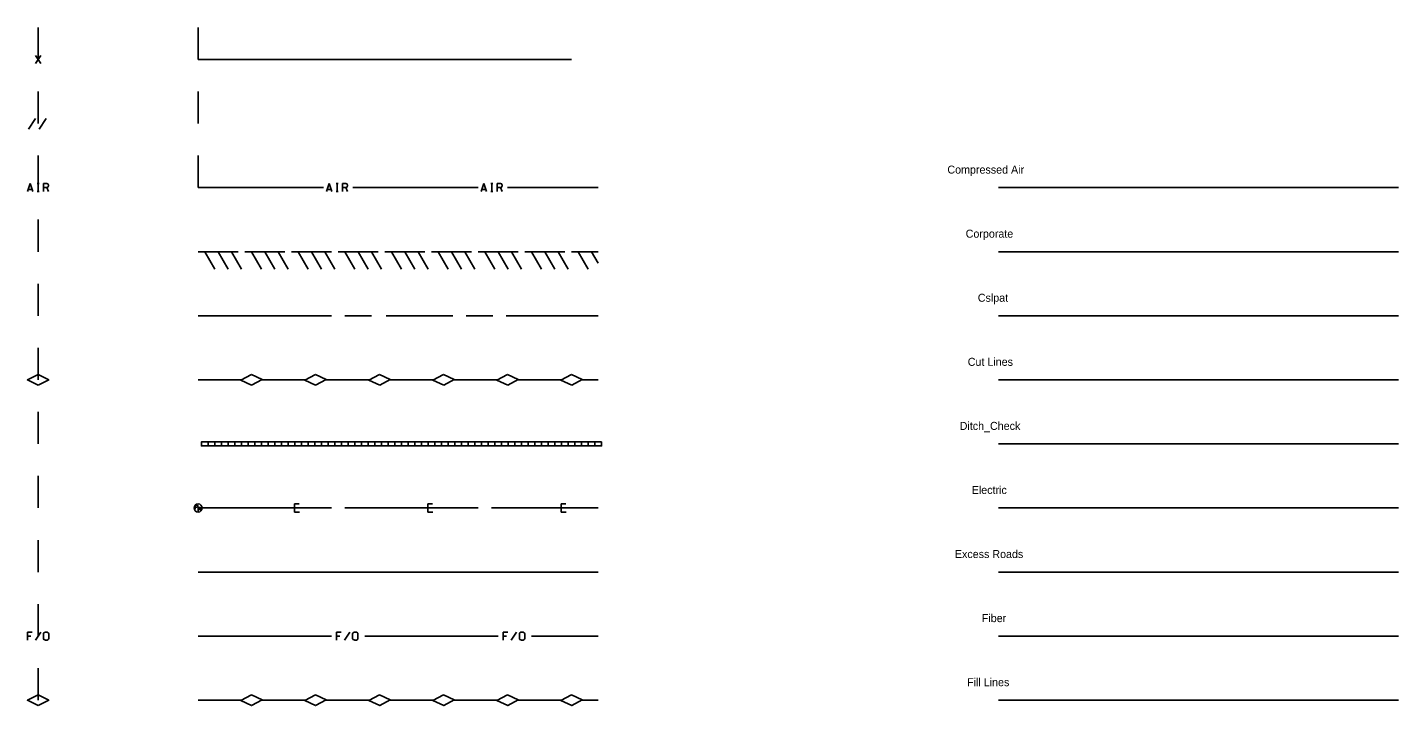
# Model space of a CAD drawing. Extents: x -0.01 to 0.85, y -1.76 to 0.02.
# Drawn here: x -0.007 to 0.85, y -0.403 to 0.02 of the extents above; entities that cross this region are included whole.
import ezdxf

# ---------------------------------------------------------------- set-up
doc = ezdxf.new("R2010")
doc.units = 0
doc.layers.add('Default', color=7, linetype='Continuous')

msp = doc.modelspace()

# ---------------------------------------------------------------- linework, layer by layer
at = {"layer": 'Default'}
for p, q in [((0, 0), (0, 0.02)), ((0.1, 0), (0.1, 0.02)), ((-0.00163, 0.0025), (0.00163, -0.0025)), ((-0.00163, -0.0025), (0.00163, 0.0025)), ((0.1, 0), (0.33333, 0)), ((0, -0.04), (0, -0.02)), ((0.1, -0.04), (0.1, -0.02)), ((-0.00597, -0.04347), (-0.00152, -0.03681)), ((0.0007, -0.04347), (0.00514, -0.03681)), ((0, -0.08), (0, -0.06)), ((0.1, -0.08), (0.1, -0.06)), ((-0.00667, -0.0825), (-0.005, -0.0775)), ((-0.00375, -0.08125), (-0.00625, -0.08125)), ((-0.005, -0.0775), (-0.00333, -0.0825)), ((-0.00062, -0.0775), (0.00062, -0.0775)), ((-0.00062, -0.0825), (0.00062, -0.0825)), ((0, -0.0775), (0, -0.0825)), ((0.00333, -0.0825), (0.00333, -0.0775)), ((0.00333, -0.0775), (0.00542, -0.0775)), ((0.00542, -0.07997), (0.00333, -0.07997)), ((0.00542, -0.07997), (0.00648, -0.0825)), ((0.1, -0.08), (0.17833, -0.08)), ((0.18022, -0.0825), (0.18188, -0.0775)), ((0.18313, -0.08125), (0.18063, -0.08125)), ((0.18188, -0.0775), (0.18355, -0.0825)), ((0.18626, -0.0775), (0.18751, -0.0775)), ((0.18626, -0.0825), (0.18751, -0.0825)), ((0.18688, -0.0775), (0.18688, -0.0825)), ((0.19022, -0.0825), (0.19022, -0.0775)), ((0.19022, -0.0775), (0.1923, -0.0775)), ((0.1923, -0.07997), (0.19022, -0.07997)), ((0.1923, -0.07997), (0.19337, -0.0825)), ((0.19667, -0.08), (0.275, -0.08)), ((0.27688, -0.0825), (0.27855, -0.0775)), ((0.2798, -0.08125), (0.2773, -0.08125)), ((0.27855, -0.0775), (0.28022, -0.0825)), ((0.28293, -0.0775), (0.28418, -0.0775)), ((0.28293, -0.0825), (0.28418, -0.0825)), ((0.28355, -0.0775), (0.28355, -0.0825)), ((0.28688, -0.0825), (0.28688, -0.0775)), ((0.28688, -0.0775), (0.28897, -0.0775)), ((0.28897, -0.07997), (0.28688, -0.07997)), ((0.28897, -0.07997), (0.29003, -0.0825)), ((0.29333, -0.08), (0.35, -0.08)), ((0.6, -0.08), (0.85, -0.08)), ((0, -0.12), (0, -0.1)), ((0.1, -0.12), (0.125, -0.12)), ((0.10417, -0.12), (0.11042, -0.13083)), ((0.1125, -0.12), (0.11875, -0.13083)), ((0.12083, -0.12), (0.12708, -0.13083)), ((0.12917, -0.12), (0.15417, -0.12)), ((0.13333, -0.12), (0.13958, -0.13083)), ((0.14167, -0.12), (0.14792, -0.13083)), ((0.15, -0.12), (0.15625, -0.13083)), ((0.15833, -0.12), (0.18333, -0.12)), ((0.1625, -0.12), (0.16875, -0.13083)), ((0.17083, -0.12), (0.17708, -0.13083)), ((0.17917, -0.12), (0.18542, -0.13083)), ((0.1875, -0.12), (0.2125, -0.12)), ((0.19167, -0.12), (0.19792, -0.13083)), ((0.2, -0.12), (0.20625, -0.13083)), ((0.20833, -0.12), (0.21458, -0.13083)), ((0.21667, -0.12), (0.24167, -0.12)), ((0.22083, -0.12), (0.22708, -0.13083)), ((0.22917, -0.12), (0.23542, -0.13083)), ((0.2375, -0.12), (0.24375, -0.13083)), ((0.24583, -0.12), (0.27083, -0.12)), ((0.25, -0.12), (0.25625, -0.13083)), ((0.25833, -0.12), (0.26458, -0.13083)), ((0.26667, -0.12), (0.27292, -0.13083)), ((0.275, -0.12), (0.3, -0.12)), ((0.27917, -0.12), (0.28542, -0.13083)), ((0.2875, -0.12), (0.29375, -0.13083)), ((0.29583, -0.12), (0.30208, -0.13083)), ((0.30417, -0.12), (0.32917, -0.12)), ((0.30833, -0.12), (0.31458, -0.13083)), ((0.31667, -0.12), (0.32292, -0.13083)), ((0.325, -0.12), (0.33125, -0.13083)), ((0.33333, -0.12), (0.35, -0.12)), ((0.3375, -0.12), (0.34375, -0.13083)), ((0.34583, -0.12), (0.35, -0.12722)), ((0.6, -0.12), (0.85, -0.12)), ((0, -0.16), (0, -0.14)), ((0.1, -0.16), (0.18333, -0.16)), ((0.19167, -0.16), (0.20833, -0.16)), ((0.2175, -0.16), (0.25917, -0.16)), ((0.2675, -0.16), (0.28417, -0.16)), ((0.2925, -0.16), (0.35, -0.16)), ((0.6, -0.16), (0.85, -0.16)), ((0, -0.2), (0, -0.18)), ((0.13325, -0.19667), (0.12667, -0.20017)), ((0.14, -0.19983), (0.13325, -0.19667)), ((0.17325, -0.19667), (0.16667, -0.20017)), ((0.18, -0.19983), (0.17325, -0.19667)), ((0.21325, -0.19667), (0.20667, -0.20017)), ((0.22, -0.19983), (0.21325, -0.19667)), ((0.25325, -0.19667), (0.24667, -0.20017)), ((0.26, -0.19983), (0.25325, -0.19667)), ((0.29325, -0.19667), (0.28667, -0.20017)), ((0.3, -0.19983), (0.29325, -0.19667)), ((0.33325, -0.19667), (0.32667, -0.20017)), ((0.34, -0.19983), (0.33325, -0.19667)), ((0.1, -0.2), (0.12667, -0.2)), ((0.12667, -0.20017), (0.13342, -0.20333)), ((0.13342, -0.20333), (0.14, -0.19983)), ((0.14, -0.2), (0.16667, -0.2)), ((0.16667, -0.20017), (0.17342, -0.20333)), ((0.17342, -0.20333), (0.18, -0.19983)), ((0.18, -0.2), (0.20667, -0.2)), ((0.20667, -0.20017), (0.21342, -0.20333)), ((0.21342, -0.20333), (0.22, -0.19983)), ((0.22, -0.2), (0.24667, -0.2)), ((0.24667, -0.20017), (0.25342, -0.20333)), ((0.25342, -0.20333), (0.26, -0.19983)), ((0.26, -0.2), (0.28667, -0.2)), ((0.28667, -0.20017), (0.29342, -0.20333)), ((0.29342, -0.20333), (0.3, -0.19983)), ((0.3, -0.2), (0.32667, -0.2)), ((0.32667, -0.20017), (0.33342, -0.20333)), ((0.33342, -0.20333), (0.34, -0.19983)), ((0.34, -0.2), (0.35, -0.2)), ((0.6, -0.2), (0.85, -0.2)), ((0, -0.24), (0, -0.22)), ((0.6, -0.24), (0.85, -0.24)), ((0, -0.28), (0, -0.26)), ((0.09816, -0.28066), (0.09816, -0.27816)), ((0.09816, -0.27816), (0.0992, -0.27816)), ((0.0992, -0.27939), (0.09816, -0.27939)), ((0.1, -0.28), (0.18333, -0.28)), ((0.10001, -0.28228), (0.10001, -0.27978)), ((0.10001, -0.27978), (0.10105, -0.27978)), ((0.10105, -0.28102), (0.10001, -0.28102)), ((0.16311, -0.2775), (0.1602, -0.2775)), ((0.1602, -0.2775), (0.1602, -0.2825)), ((0.16228, -0.28), (0.1602, -0.28)), ((0.1602, -0.2825), (0.16332, -0.2825)), ((0.19167, -0.28), (0.275, -0.28)), ((0.24645, -0.2775), (0.24353, -0.2775)), ((0.24353, -0.2775), (0.24353, -0.2825)), ((0.24561, -0.28), (0.24353, -0.28)), ((0.24353, -0.2825), (0.24666, -0.2825)), ((0.28333, -0.28), (0.35, -0.28)), ((0.32978, -0.2775), (0.32686, -0.2775)), ((0.32686, -0.2775), (0.32686, -0.2825)), ((0.32895, -0.28), (0.32686, -0.28)), ((0.32686, -0.2825), (0.32999, -0.2825)), ((0.6, -0.28), (0.85, -0.28)), ((0, -0.32), (0, -0.3)), ((0.1, -0.32), (0.14167, -0.32)), ((0.1, -0.32), (0.35, -0.32)), ((0.18333, -0.32), (0.225, -0.32)), ((0.26667, -0.32), (0.30833, -0.32)), ((0.6, -0.32), (0.85, -0.32)), ((0, -0.36), (0, -0.34)), ((-0.00375, -0.3575), (-0.00667, -0.3575)), ((-0.00667, -0.3575), (-0.00667, -0.3625)), ((-0.00167, -0.3625), (0.00167, -0.3575)), ((0.00335, -0.36156), (0.00335, -0.35844)), ((0.00669, -0.36156), (0.00669, -0.35844)), ((0.1894, -0.3575), (0.18649, -0.3575)), ((0.18649, -0.3575), (0.18649, -0.3625)), ((0.19149, -0.3625), (0.19482, -0.3575)), ((0.19651, -0.36156), (0.19651, -0.35844)), ((0.19984, -0.36156), (0.19984, -0.35844)), ((0.29357, -0.3575), (0.29065, -0.3575)), ((0.29065, -0.3575), (0.29065, -0.3625)), ((0.29565, -0.3625), (0.29899, -0.3575)), ((0.30067, -0.36156), (0.30067, -0.35844)), ((0.30401, -0.36156), (0.30401, -0.35844)), ((-0.00667, -0.35997), (-0.0046, -0.35997)), ((0.1, -0.36), (0.18333, -0.36)), ((0.18649, -0.35997), (0.18856, -0.35997)), ((0.20417, -0.36), (0.2875, -0.36)), ((0.29065, -0.35997), (0.29272, -0.35997)), ((0.30833, -0.36), (0.35, -0.36)), ((0.6, -0.36), (0.85, -0.36)), ((0, -0.4), (0, -0.38)), ((0.1, -0.4), (0.12667, -0.4)), ((0.14, -0.4), (0.16667, -0.4)), ((0.18, -0.4), (0.20667, -0.4)), ((0.22, -0.4), (0.24667, -0.4)), ((0.26, -0.4), (0.28667, -0.4)), ((0.3, -0.4), (0.32667, -0.4)), ((0.34, -0.4), (0.35, -0.4)), ((0.6, -0.4), (0.85, -0.4))]:
    msp.add_line(p, q, dxfattribs=at)
for points in [[(0.00542, -0.0775), (0.00604, -0.07771), (0.00648, -0.07852), (0.00648, -0.07896), (0.00604, -0.07979), (0.00542, -0.07997)], [(0.1923, -0.0775), (0.19292, -0.07771), (0.19337, -0.07852), (0.19337, -0.07896), (0.19292, -0.07979), (0.1923, -0.07997)], [(0.28897, -0.0775), (0.28959, -0.07771), (0.29003, -0.07852), (0.29003, -0.07896), (0.28959, -0.07979), (0.28897, -0.07997)], [(0.0992, -0.27816), (0.09951, -0.27826), (0.09973, -0.27866), (0.09973, -0.27889), (0.09951, -0.2793), (0.0992, -0.27939)], [(0.10105, -0.27978), (0.10137, -0.27989), (0.10159, -0.28029), (0.10159, -0.28051), (0.10137, -0.28093), (0.10105, -0.28102)], [(0.00335, -0.35844), (0.00347, -0.3581), (0.00372, -0.35785), (0.00423, -0.35761), (0.00473, -0.3575), (0.0054, -0.3575), (0.00573, -0.35759), (0.00635, -0.35787), (0.00658, -0.3581), (0.00669, -0.35844)], [(0.19651, -0.35844), (0.19662, -0.3581), (0.19687, -0.35785), (0.19739, -0.35761), (0.19788, -0.3575), (0.19855, -0.3575), (0.19888, -0.35759), (0.19951, -0.35787), (0.19973, -0.3581), (0.19984, -0.35844)], [(0.30067, -0.35844), (0.30078, -0.3581), (0.30104, -0.35785), (0.30155, -0.35761), (0.30205, -0.3575), (0.30272, -0.3575), (0.30304, -0.35759), (0.30367, -0.35787), (0.3039, -0.3581), (0.30401, -0.35844)], [(0.00335, -0.36156), (0.00347, -0.3619), (0.00372, -0.36215), (0.00423, -0.36239), (0.00473, -0.3625), (0.0054, -0.3625), (0.00573, -0.36241), (0.00635, -0.36213), (0.00658, -0.3619), (0.00669, -0.36156)], [(0.19651, -0.36156), (0.19662, -0.3619), (0.19687, -0.36215), (0.19739, -0.36239), (0.19788, -0.3625), (0.19855, -0.3625), (0.19888, -0.36241), (0.19951, -0.36213), (0.19973, -0.3619), (0.19984, -0.36156)], [(0.30067, -0.36156), (0.30078, -0.3619), (0.30104, -0.36215), (0.30155, -0.36239), (0.30205, -0.3625), (0.30272, -0.3625), (0.30304, -0.36241), (0.30367, -0.36213), (0.3039, -0.3619), (0.30401, -0.36156)]]:
    msp.add_lwpolyline(points, dxfattribs=at)
for points in [[(0, -0.20333), (-0.00667, -0.2), (0, -0.19667), (0.00667, -0.2)], [(0.10625, -0.23875), (0.10208, -0.23875), (0.10208, -0.24125), (0.10625, -0.24125)], [(0.11042, -0.23875), (0.10625, -0.23875), (0.10625, -0.24125), (0.11042, -0.24125)], [(0.11458, -0.23875), (0.11042, -0.23875), (0.11042, -0.24125), (0.11458, -0.24125)], [(0.11875, -0.23875), (0.11458, -0.23875), (0.11458, -0.24125), (0.11875, -0.24125)], [(0.12292, -0.23875), (0.11875, -0.23875), (0.11875, -0.24125), (0.12292, -0.24125)], [(0.12708, -0.23875), (0.12292, -0.23875), (0.12292, -0.24125), (0.12708, -0.24125)], [(0.13125, -0.23875), (0.12708, -0.23875), (0.12708, -0.24125), (0.13125, -0.24125)], [(0.13542, -0.23875), (0.13125, -0.23875), (0.13125, -0.24125), (0.13542, -0.24125)], [(0.13958, -0.23875), (0.13542, -0.23875), (0.13542, -0.24125), (0.13958, -0.24125)], [(0.14375, -0.23875), (0.13958, -0.23875), (0.13958, -0.24125), (0.14375, -0.24125)], [(0.14792, -0.23875), (0.14375, -0.23875), (0.14375, -0.24125), (0.14792, -0.24125)], [(0.15208, -0.23875), (0.14792, -0.23875), (0.14792, -0.24125), (0.15208, -0.24125)], [(0.15625, -0.23875), (0.15208, -0.23875), (0.15208, -0.24125), (0.15625, -0.24125)], [(0.16042, -0.23875), (0.15625, -0.23875), (0.15625, -0.24125), (0.16042, -0.24125)], [(0.16458, -0.23875), (0.16042, -0.23875), (0.16042, -0.24125), (0.16458, -0.24125)], [(0.16875, -0.23875), (0.16458, -0.23875), (0.16458, -0.24125), (0.16875, -0.24125)], [(0.17292, -0.23875), (0.16875, -0.23875), (0.16875, -0.24125), (0.17292, -0.24125)], [(0.17708, -0.23875), (0.17292, -0.23875), (0.17292, -0.24125), (0.17708, -0.24125)], [(0.18125, -0.23875), (0.17708, -0.23875), (0.17708, -0.24125), (0.18125, -0.24125)], [(0.18542, -0.23875), (0.18125, -0.23875), (0.18125, -0.24125), (0.18542, -0.24125)], [(0.18958, -0.23875), (0.18542, -0.23875), (0.18542, -0.24125), (0.18958, -0.24125)], [(0.19375, -0.23875), (0.18958, -0.23875), (0.18958, -0.24125), (0.19375, -0.24125)], [(0.19792, -0.23875), (0.19375, -0.23875), (0.19375, -0.24125), (0.19792, -0.24125)], [(0.20208, -0.23875), (0.19792, -0.23875), (0.19792, -0.24125), (0.20208, -0.24125)], [(0.20625, -0.23875), (0.20208, -0.23875), (0.20208, -0.24125), (0.20625, -0.24125)], [(0.21042, -0.23875), (0.20625, -0.23875), (0.20625, -0.24125), (0.21042, -0.24125)], [(0.21458, -0.23875), (0.21042, -0.23875), (0.21042, -0.24125), (0.21458, -0.24125)], [(0.21875, -0.23875), (0.21458, -0.23875), (0.21458, -0.24125), (0.21875, -0.24125)], [(0.22292, -0.23875), (0.21875, -0.23875), (0.21875, -0.24125), (0.22292, -0.24125)], [(0.22708, -0.23875), (0.22292, -0.23875), (0.22292, -0.24125), (0.22708, -0.24125)], [(0.23125, -0.23875), (0.22708, -0.23875), (0.22708, -0.24125), (0.23125, -0.24125)], [(0.23542, -0.23875), (0.23125, -0.23875), (0.23125, -0.24125), (0.23542, -0.24125)], [(0.23958, -0.23875), (0.23542, -0.23875), (0.23542, -0.24125), (0.23958, -0.24125)], [(0.24375, -0.23875), (0.23958, -0.23875), (0.23958, -0.24125), (0.24375, -0.24125)], [(0.24792, -0.23875), (0.24375, -0.23875), (0.24375, -0.24125), (0.24792, -0.24125)], [(0.25208, -0.23875), (0.24792, -0.23875), (0.24792, -0.24125), (0.25208, -0.24125)], [(0.25625, -0.23875), (0.25208, -0.23875), (0.25208, -0.24125), (0.25625, -0.24125)], [(0.26042, -0.23875), (0.25625, -0.23875), (0.25625, -0.24125), (0.26042, -0.24125)], [(0.26458, -0.23875), (0.26042, -0.23875), (0.26042, -0.24125), (0.26458, -0.24125)], [(0.26875, -0.23875), (0.26458, -0.23875), (0.26458, -0.24125), (0.26875, -0.24125)], [(0.27292, -0.23875), (0.26875, -0.23875), (0.26875, -0.24125), (0.27292, -0.24125)], [(0.27708, -0.23875), (0.27292, -0.23875), (0.27292, -0.24125), (0.27708, -0.24125)], [(0.28125, -0.23875), (0.27708, -0.23875), (0.27708, -0.24125), (0.28125, -0.24125)], [(0.28542, -0.23875), (0.28125, -0.23875), (0.28125, -0.24125), (0.28542, -0.24125)], [(0.28958, -0.23875), (0.28542, -0.23875), (0.28542, -0.24125), (0.28958, -0.24125)], [(0.29375, -0.23875), (0.28958, -0.23875), (0.28958, -0.24125), (0.29375, -0.24125)], [(0.29792, -0.23875), (0.29375, -0.23875), (0.29375, -0.24125), (0.29792, -0.24125)], [(0.30208, -0.23875), (0.29792, -0.23875), (0.29792, -0.24125), (0.30208, -0.24125)], [(0.30625, -0.23875), (0.30208, -0.23875), (0.30208, -0.24125), (0.30625, -0.24125)], [(0.31042, -0.23875), (0.30625, -0.23875), (0.30625, -0.24125), (0.31042, -0.24125)], [(0.31458, -0.23875), (0.31042, -0.23875), (0.31042, -0.24125), (0.31458, -0.24125)], [(0.31875, -0.23875), (0.31458, -0.23875), (0.31458, -0.24125), (0.31875, -0.24125)], [(0.32292, -0.23875), (0.31875, -0.23875), (0.31875, -0.24125), (0.32292, -0.24125)], [(0.32708, -0.23875), (0.32292, -0.23875), (0.32292, -0.24125), (0.32708, -0.24125)], [(0.33125, -0.23875), (0.32708, -0.23875), (0.32708, -0.24125), (0.33125, -0.24125)], [(0.33542, -0.23875), (0.33125, -0.23875), (0.33125, -0.24125), (0.33542, -0.24125)], [(0.33958, -0.23875), (0.33542, -0.23875), (0.33542, -0.24125), (0.33958, -0.24125)], [(0.34375, -0.23875), (0.33958, -0.23875), (0.33958, -0.24125), (0.34375, -0.24125)], [(0.34792, -0.23875), (0.34375, -0.23875), (0.34375, -0.24125), (0.34792, -0.24125)], [(0.35208, -0.23875), (0.34792, -0.23875), (0.34792, -0.24125), (0.35208, -0.24125)], [(0, -0.40333), (-0.00667, -0.4), (0, -0.39667), (0.00667, -0.4)], [(0.13325, -0.39667), (0.12667, -0.40017), (0.13342, -0.40333), (0.14, -0.39983)], [(0.17325, -0.39667), (0.16667, -0.40017), (0.17342, -0.40333), (0.18, -0.39983)], [(0.21325, -0.39667), (0.20667, -0.40017), (0.21342, -0.40333), (0.22, -0.39983)], [(0.25325, -0.39667), (0.24667, -0.40017), (0.25342, -0.40333), (0.26, -0.39983)], [(0.29325, -0.39667), (0.28667, -0.40017), (0.29342, -0.40333), (0.3, -0.39983)], [(0.33325, -0.39667), (0.32667, -0.40017), (0.33342, -0.40333), (0.34, -0.39983)]]:
    msp.add_lwpolyline(points, close=True, dxfattribs=at)
msp.add_circle((0.1, -0.28), 0.0025, dxfattribs=at)

# ---------------------------------------------------------------- texts
for s, p in [('Compressed Air', (0.56811, -0.07125)), ('Corporate', (0.57953, -0.11125)), ('Cslpat', (0.58711, -0.15125)), ('Cut Lines', (0.58083, -0.19125)), ('Ditch_Check', (0.57579, -0.23125)), ('Electric', (0.58331, -0.27125)), ('Excess Roads', (0.57278, -0.31125)), ('Fiber', (0.58963, -0.35125)), ('Fill Lines', (0.58042, -0.39125))]:
    msp.add_text(s, height=0.005, dxfattribs=at).set_placement(p)

doc.saveas('drawing.dxf')
